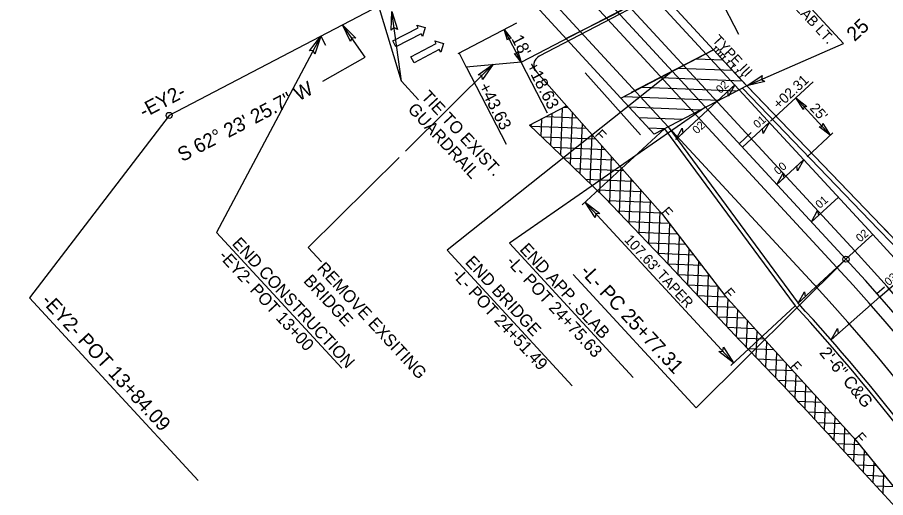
# Model space of a CAD drawing. Extents: x 1702862 to 1704514, y 793768 to 796215.
# Drawn here: x 1703316.6 to 1703743.4, y 794685.6 to 794921.9 of the extents above; entities that cross this region are included whole.
import ezdxf

# ---------------------------------------------------------------- set-up
doc = ezdxf.new("R2010")
doc.units = 0
for name, color, linetype in [('Exist Horizontal Alignment', 7, 'Continuous'), ('Exist Horizontal Alignment Direction Label', 7, 'Continuous'), ('Exist Horizontal Alignment Station Label', 7, 'Continuous'), ('Exist Horizontal Alignment Tick Small', 7, 'Continuous'), ('Old_Level_30', 7, 'Continuous'), ('Prop Approach Slab', 7, 'Continuous'), ('Prop Conc 2ft 6in Curb and Gutter', 7, 'Continuous'), ('Prop Conc Shoulder Berm Gutter', 7, 'Continuous'), ('Prop Dimension', 7, 'Continuous'), ('Prop Dimension Text', 7, 'Continuous'), ('Prop DSN Text', 7, 'Continuous'), ('Prop EOT', 7, 'Continuous'), ('Prop Guardrail', 7, 'Continuous'), ('Prop Guardrail Anchor Unit CELL', 7, 'Continuous'), ('Prop Horizontal Alignment', 7, 'Continuous'), ('Prop Horizontal Alignment Station Label', 7, 'Continuous'), ('Prop Horizontal Alignment Tick Label', 7, 'Continuous'), ('Prop Horizontal Alignment Tick Large', 7, 'Continuous'), ('Prop Horizontal Alignment Tick Small', 7, 'Continuous'), ('Prop Lane Arrow CELL', 7, 'Continuous'), ('Prop Lane Lines', 7, 'Continuous'), ('Prop Leader Line Medium', 7, 'Continuous'), ('Prop Paved Shoulder', 7, 'Continuous'), ('Prop Rem of Exist Asph Pvmt', 7, 'Continuous'), ('Prop Roadway Bridge', 7, 'Continuous'), ('Prop SS Fill Line', 7, 'Continuous'), ('Prop SS Misc', 7, 'Continuous'), ('Prop Structure Anchor Unit CELL', 7, 'Continuous'), ('Prop Superelevation  Arrow CELL', 7, 'Continuous'), ('Prop Superelevation Label', 7, 'Continuous'), ('Prop Terminator CELL', 7, 'Continuous')]:
    doc.layers.add(name, color=color, linetype=linetype)

msp = doc.modelspace()

# ---------------------------------------------------------------- linework, layer by layer
at = {"layer": 'Exist Horizontal Alignment'}
msp.add_line((1703731.56, 795051.6), (1703391.21, 794873.6), dxfattribs=at)
at = {"layer": 'Exist Horizontal Alignment Direction Label'}
msp.add_lwpolyline([(1703466.74, 794890.55), (1703487.62, 794902.29), (1703476.47, 794918.19)], dxfattribs=at)
at = {"layer": 'Exist Horizontal Alignment Station Label'}
msp.add_lwpolyline([(1703391.21, 794873.6), (1703322.49, 794783.98), (1703405.46, 794694.11)], dxfattribs=at)
msp.add_circle((1703391.21, 794873.6), 1.5, dxfattribs=at)
at = {"layer": 'Exist Horizontal Alignment Tick Small'}
msp.add_line((1703465.72, 794912.57), (1703468.04, 794908.14), dxfattribs=at)
at = {"layer": 'Old_Level_30'}
msp.add_line((1703622.97, 794864.03), (1703595.71, 794894.58), dxfattribs=at)
at = {"layer": 'Prop Approach Slab'}
for p, q in [((1703658.78, 794905.92), (1703618.37, 794884.83)), ((1703658.78, 794905.92), (1703675.15, 794888.19)), ((1703650.4, 794901.54), (1703663.3, 794901.02)), ((1703641.5, 794896.89), (1703668.1, 794895.83)), ((1703675.15, 794888.19), (1703629.69, 794864.45)), ((1703632.59, 794892.25), (1703672.89, 794890.63)), ((1703623.69, 794887.6), (1703670.44, 794885.73)), ((1703613.32, 794882.19), (1703629.69, 794864.45)), ((1703614.79, 794882.95), (1703661.54, 794881.08)), ((1703617.33, 794877.84), (1703652.64, 794876.43)), ((1703622.13, 794872.65), (1703643.73, 794871.78)), ((1703626.93, 794867.45), (1703634.83, 794867.14))]:
    msp.add_line(p, q, dxfattribs=at)
msp.add_lwpolyline([(1703658.78, 794905.92), (1703675.15, 794888.19), (1703629.69, 794864.45), (1703613.32, 794882.19)], close=True, dxfattribs=at)
at = {"layer": 'Prop Conc 2ft 6in Curb and Gutter'}
msp.add_line((1703634.75, 794867.09), (1703699, 794779.93), dxfattribs=at)
msp.add_arc((1702985.28, 794122.36), 970.46, 32.25438, 42.65517, dxfattribs=at)
at = {"layer": 'Prop Conc Shoulder Berm Gutter'}
msp.add_line((1703675.15, 794888.19), (1703741.57, 794819.22), dxfattribs=at)
msp.add_arc((1703001.93, 794109.28), 1025.22, 38.16066, 43.82598, dxfattribs=at)
at = {"layer": 'Prop Dimension'}
for p, q in [((1703594.25, 794829.71), (1703634.75, 794867.09)), ((1703595.68, 794831.04), (1703668.69, 794751.95)), ((1703667.25, 794750.62), (1703699, 794779.93))]:
    msp.add_line(p, q, dxfattribs=at)
at = {"layer": 'Prop Dimension Text'}
for p, q in [((1703653.98, 794946.7), (1703671.12, 794913.52)), ((1703533.31, 794904.01), (1703562.18, 794919.2)), ((1703555.92, 794915.89), (1703564.25, 794899.77)), ((1703557.01, 794859.29), (1703537.31, 794897.44)), ((1703577.2, 794874.69), (1703564.25, 794899.77))]:
    msp.add_line(p, q, dxfattribs=at)
at = {"layer": 'Prop EOT'}
for p, q in [((1703259.9, 795332.15), (1703737.14, 794815.13)), ((1703418.98, 795103.79), (1703636.58, 794868.05)), ((1703564.25, 794899.77), (1703653.98, 794946.7)), ((1703533.7, 794904.22), (1703537.26, 794897.42)), ((1703564.25, 794899.77), (1703537.26, 794897.42)), ((1703636.58, 794868.05), (1703700.4, 794781.22))]:
    msp.add_line(p, q, dxfattribs=at)
msp.add_lwpolyline([(1703586.27, 794911.5), (1703608.79, 794922.72), (1703631.89, 794935.05)], dxfattribs=at)
for radius, start, end in [(1018, 14.75888, 42.70907), (968, 32.4282, 42.70916)]:
    msp.add_arc((1702989.11, 794124.65), radius, start, end, dxfattribs=at)
at = {"layer": 'Prop Guardrail'}
msp.add_line((1703741.57, 794819.22), (1703671.5, 794892.15), dxfattribs=at)
msp.add_arc((1703002.29, 794108.92), 1025.21, 38.32941, 43.85449, dxfattribs=at)
at = {"layer": 'Prop Horizontal Alignment'}
msp.add_line((1703246.67, 795319.94), (1703723.92, 794802.92), dxfattribs=at)
msp.add_arc((1702989.11, 794124.65), 1000, 351.25916, 42.70907, dxfattribs=at)
at = {"layer": 'Prop Horizontal Alignment Station Label'}
for p in [(1703723.92, 794802.92), (1703589.75, 794795.36)]:
    msp.add_line(p, (1703650.3, 794729.77), dxfattribs=at)
msp.add_circle((1703723.92, 794802.92), 1.5, dxfattribs=at)
at = {"layer": 'Prop Horizontal Alignment Tick Large'}
msp.add_line((1703671.48, 794859.73), (1703677.36, 794865.16), dxfattribs=at)
at = {"layer": 'Prop Horizontal Alignment Tick Small'}
msp.add_line((1703739.12, 794786.08), (1703742.87, 794789.38), dxfattribs=at)
at = {"layer": 'Prop Lane Arrow CELL'}
for p, q in [((1703513.59, 794916.75), (1703512.9, 794918.08)), ((1703512.9, 794918.08), (1703517.12, 794916.8)), ((1703501.19, 794910.26), (1703513.59, 794916.75)), ((1703515.12, 794913.83), (1703502.72, 794907.34)), ((1703515.82, 794912.5), (1703515.12, 794913.83)), ((1703517.12, 794916.8), (1703515.82, 794912.5)), ((1703502.72, 794907.34), (1703501.19, 794910.26)), ((1703522.46, 794908.94), (1703521.77, 794910.27)), ((1703521.77, 794910.27), (1703526, 794908.99)), ((1703510.06, 794902.45), (1703522.46, 794908.94)), ((1703524, 794906.02), (1703511.59, 794899.52)), ((1703524.69, 794904.69), (1703524, 794906.02)), ((1703526, 794908.99), (1703524.69, 794904.69)), ((1703511.59, 794899.52), (1703510.06, 794902.45))]:
    msp.add_line(p, q, dxfattribs=at)
at = {"layer": 'Prop Lane Lines'}
for p, q in [((1703599.26, 794946.81), (1703728.33, 794806.99)), ((1703591.49, 794937.54), (1703719.51, 794798.85)), ((1703636.58, 794868.05), (1703710.03, 794788.48))]:
    msp.add_line(p, q, dxfattribs=at)
for radius, start in [(1006, 0.00687), (994, 359.40932), (980, 359.40932)]:
    msp.add_arc((1702989.11, 794124.65), radius, start, 42.70907, dxfattribs=at)
at = {"layer": 'Prop Leader Line Medium'}
for p, q in [((1703505.35, 794890.4), (1703492.38, 794933.6)), ((1703505.35, 794890.4), (1703500.62, 794924.67)), ((1703465.72, 794912.57), (1703414.54, 794816.04)), ((1703507.34, 794856.01), (1703550.53, 794898.76)), ((1703638.58, 794895.38), (1703527.8, 794807.39)), ((1703505.35, 794890.4), (1703513.76, 794881.29)), ((1703654.95, 794877.64), (1703558.46, 794810.73)), ((1703459.59, 794808.73), (1703504.23, 794852.93)), ((1703414.54, 794816.04), (1703476.14, 794749.31)), ((1703466.09, 794801.68), (1703459.59, 794808.73)), ((1703527.8, 794807.39), (1703589.4, 794740.66)), ((1703558.46, 794810.73), (1703619.32, 794744.8))]:
    msp.add_line(p, q, dxfattribs=at)
msp.add_lwpolyline([(1703675.15, 794888.19), (1703722.72, 794909.06), (1703678.78, 794956.66)], dxfattribs=at)
at = {"layer": 'Prop Paved Shoulder'}
msp.add_line((1703673, 794887.06), (1703739.89, 794817.6), dxfattribs=at)
msp.add_arc((1703001.93, 794109.28), 1022.89, 38.16066, 43.82598, dxfattribs=at)
at = {"layer": 'Prop Rem of Exist Asph Pvmt'}
for p, q in [((1703584.45, 794877.22), (1703583.53, 794854.21)), ((1703585.42, 794877.73), (1703587.05, 794877.66)), ((1703574.23, 794871.86), (1703573.9, 794863.49)), ((1703576.55, 794873.08), (1703591.64, 794872.47)), ((1703579.34, 794874.54), (1703578.71, 794858.85)), ((1703589.37, 794875.04), (1703588.35, 794849.57)), ((1703568.82, 794868.38), (1703596.23, 794867.29)), ((1703569.12, 794869.19), (1703569.08, 794868.13)), ((1703594.16, 794869.63), (1703593.17, 794844.93)), ((1703574.24, 794863.16), (1703600.82, 794862.1)), ((1703598.94, 794864.22), (1703597.99, 794840.29)), ((1703603.73, 794858.81), (1703602.81, 794835.65)), ((1703579.66, 794857.94), (1703605.41, 794856.91)), ((1703585.08, 794852.72), (1703610, 794851.72)), ((1703608.52, 794853.39), (1703607.62, 794830.82)), ((1703590.5, 794847.5), (1703614.58, 794846.54)), ((1703613.31, 794847.98), (1703612.42, 794825.77)), ((1703595.93, 794842.28), (1703619.17, 794841.35)), ((1703618.09, 794842.57), (1703617.22, 794820.71)), ((1703601.35, 794837.06), (1703623.76, 794836.16)), ((1703622.88, 794837.16), (1703622.02, 794815.66)), ((1703606.65, 794831.84), (1703628.35, 794830.97)), ((1703627.67, 794831.74), (1703626.82, 794810.61)), ((1703611.59, 794826.64), (1703632.94, 794825.79)), ((1703632.46, 794826.33), (1703631.63, 794805.55)), ((1703616.53, 794821.44), (1703637.01, 794820.62)), ((1703637.22, 794820.35), (1703636.43, 794800.5)), ((1703621.47, 794816.24), (1703640.98, 794815.46)), ((1703641.98, 794814.15), (1703641.23, 794795.39)), ((1703626.42, 794811.03), (1703644.94, 794810.29)), ((1703646.73, 794807.96), (1703646.03, 794790.27)), ((1703631.36, 794805.83), (1703648.91, 794805.13)), ((1703636.3, 794800.63), (1703652.87, 794799.97)), ((1703651.49, 794801.77), (1703650.83, 794785.15)), ((1703641.18, 794795.43), (1703656.84, 794794.81)), ((1703656.25, 794795.57), (1703655.62, 794780.04)), ((1703646.06, 794790.23), (1703660.8, 794789.64)), ((1703661, 794789.38), (1703660.42, 794774.92)), ((1703650.94, 794785.03), (1703664.85, 794784.48)), ((1703665.77, 794783.46), (1703665.22, 794769.81)), ((1703655.82, 794779.83), (1703669.55, 794779.29)), ((1703670.56, 794778.17), (1703670.02, 794764.7)), ((1703660.69, 794774.64), (1703674.26, 794774.09)), ((1703675.35, 794772.88), (1703674.83, 794759.67)), ((1703665.57, 794769.44), (1703678.96, 794768.9)), ((1703670.47, 794764.24), (1703683.67, 794763.71)), ((1703680.15, 794767.59), (1703679.63, 794754.65)), ((1703684.94, 794762.31), (1703684.43, 794749.62)), ((1703675.44, 794759.03), (1703688.37, 794758.52)), ((1703689.73, 794757.02), (1703689.23, 794744.59)), ((1703680.41, 794753.83), (1703693.08, 794753.32)), ((1703694.52, 794751.73), (1703694.04, 794739.57)), ((1703685.38, 794748.63), (1703697.79, 794748.13)), ((1703690.35, 794743.42), (1703702.51, 794742.94)), ((1703699.32, 794746.45), (1703698.84, 794734.54)), ((1703704.11, 794741.18), (1703703.64, 794729.5)), ((1703695.32, 794738.22), (1703707.23, 794737.75)), ((1703708.9, 794735.91), (1703708.44, 794724.38)), ((1703700.29, 794733.02), (1703711.96, 794732.55)), ((1703713.7, 794730.64), (1703713.24, 794719.19)), ((1703705.23, 794727.82), (1703716.68, 794727.36)), ((1703710.07, 794722.62), (1703721.41, 794722.17)), ((1703718.49, 794725.37), (1703718.03, 794713.96)), ((1703714.86, 794717.42), (1703726.13, 794716.97)), ((1703723.28, 794720.1), (1703722.83, 794708.7)), ((1703728.08, 794714.84), (1703727.62, 794703.44)), ((1703719.61, 794712.23), (1703730.61, 794711.79)), ((1703732.85, 794709.01), (1703732.41, 794698.21)), ((1703724.34, 794707.04), (1703734.77, 794706.62)), ((1703729.08, 794701.84), (1703738.93, 794701.45)), ((1703737.61, 794703.09), (1703737.21, 794693.01)), ((1703733.85, 794696.65), (1703743.09, 794696.28)), ((1703742.38, 794697.16), (1703742.01, 794687.84)), ((1703738.66, 794691.45), (1703747.25, 794691.11))]:
    msp.add_line(p, q, dxfattribs=at)
for points in [[(1703568.38, 794868.8), (1703586.5, 794878.29)], [(1703579.1, 794858.48), (1703568.38, 794868.8)], [(1703579.1, 794858.48), (1703589.48, 794848.49)], [(1703669.4, 794765.36), (1703636.82, 794800.09), (1703605.39, 794833.16), (1703589.48, 794848.49)]]:
    msp.add_lwpolyline(points, dxfattribs=at)
msp.add_spline([(1703779.68, 794644.96), (1703761.75, 794665.91), (1703731.32, 794699.4), (1703700.82, 794732.47), (1703669.4, 794765.36)], degree=3, dxfattribs=at)
at = {"layer": 'Prop Roadway Bridge'}
for p, q in [((1703525.81, 795049.97), (1703658.78, 794905.92)), ((1703480.41, 795026.18), (1703613.32, 794882.19)), ((1703613.32, 794882.19), (1703658.78, 794905.92))]:
    msp.add_line(p, q, dxfattribs=at)
at = {"layer": 'Prop SS Fill Line'}
for p, q in [((1703689.78, 794963.74), (1703573.15, 794902.74)), ((1703571.72, 794894.99), (1703633.73, 794824.89)), ((1703633.73, 794824.89), (1703664.31, 794785.07)), ((1703664.31, 794785.07), (1703697.03, 794748.96)), ((1703697.03, 794748.96), (1703728.84, 794713.99)), ((1703728.84, 794713.99), (1703758.51, 794677.1))]:
    msp.add_line(p, q, dxfattribs=at)
msp.add_arc((1703575.47, 794898.31), 5, 117.6095, 221.4926, dxfattribs=at)
at = {"layer": 'Prop Structure Anchor Unit CELL'}
for p, q in [((1703658.78, 794905.92), (1703660.25, 794907.28)), ((1703658.78, 794905.92), (1703671.5, 794892.15)), ((1703659.84, 794904.78), (1703661.31, 794906.13)), ((1703659.86, 794907.7), (1703660.64, 794906.86)), ((1703660.92, 794906.55), (1703661.7, 794905.71)), ((1703661.98, 794905.41), (1703662.76, 794904.56)), ((1703660.9, 794903.63), (1703662.37, 794904.98)), ((1703661.96, 794902.48), (1703663.43, 794903.84)), ((1703663.02, 794901.33), (1703664.49, 794902.69)), ((1703663.04, 794904.26), (1703663.82, 794903.42)), ((1703664.1, 794903.11), (1703664.88, 794902.27)), ((1703666.22, 794900.81), (1703667, 794899.97)), ((1703665.14, 794899.04), (1703666.61, 794900.39)), ((1703667.26, 794896.74), (1703668.73, 794898.1)), ((1703668.34, 794898.52), (1703669.12, 794897.68)), ((1703669.38, 794894.44), (1703670.85, 794895.8)), ((1703670.46, 794896.22), (1703671.23, 794895.38)), ((1703671.5, 794892.15), (1703672.97, 794893.5)), ((1703672.58, 794893.92), (1703673.35, 794893.08))]:
    msp.add_line(p, q, dxfattribs=at)
at = {"layer": 'Prop Superelevation  Arrow CELL'}
for p, q in [((1703656.09, 794876.4), (1703669.31, 794888.61)), ((1703640.32, 794861.85), (1703656.09, 794876.4)), ((1703673.05, 794858.03), (1703686.27, 794870.24)), ((1703690, 794839.66), (1703703.23, 794851.87)), ((1703706.96, 794821.29), (1703720.19, 794833.5)), ((1703723.92, 794802.92), (1703737.14, 794815.13)), ((1703723.92, 794802.92), (1703700.48, 794781.29)), ((1703740.64, 794784.34), (1703754.17, 794796.22)), ((1703740.64, 794784.34), (1703716.65, 794763.28))]:
    msp.add_line(p, q, dxfattribs=at)
for points in [[(1703669.31, 794888.61), (1703666.26, 794883.07), (1703665.92, 794885.48)], [(1703640.32, 794861.85), (1703643.37, 794867.39), (1703643.72, 794864.98)], [(1703686.27, 794870.24), (1703683.22, 794864.7), (1703682.87, 794867.11)], [(1703703.23, 794851.87), (1703700.18, 794846.33), (1703699.83, 794848.74)], [(1703690, 794839.66), (1703693.05, 794845.2), (1703693.4, 794842.8)], [(1703706.96, 794821.29), (1703710.01, 794826.83), (1703710.36, 794824.43)], [(1703700.48, 794781.29), (1703703.53, 794786.83), (1703703.87, 794784.42)], [(1703716.65, 794763.28), (1703719.84, 794768.75), (1703720.13, 794766.34)]]:
    msp.add_lwpolyline(points, close=True, dxfattribs=at)
at = {"layer": 'Prop Superelevation Label'}
for p, q in [((1703686.79, 794870.72), (1703707.87, 794890.18)), ((1703699.24, 794882.21), (1703716.21, 794863.85)), ((1703704.77, 794853.3), (1703717.55, 794865.09))]:
    msp.add_line(p, q, dxfattribs=at)
for points in [[(1703702.97, 794876.47), (1703699.24, 794882.21), (1703704.73, 794878.04), (1703703.26, 794877.86)], [(1703712.48, 794869.6), (1703716.21, 794863.85), (1703710.72, 794868.02), (1703712.19, 794868.2)]]:
    msp.add_lwpolyline(points, close=True, dxfattribs=at)
at = {"layer": 'Prop Terminator CELL'}
for points in [[(1703500.32, 794915.54), (1703500.62, 794924.67), (1703503.45, 794915.92), (1703501.7, 794916.85)], [(1703480.37, 794909.93), (1703476.47, 794918.19), (1703482.97, 794911.7), (1703481, 794911.72)], [(1703557.57, 794910.66), (1703555.92, 794915.89), (1703559.27, 794911.51), (1703558.1, 794911.68)], [(1703460.12, 794905.35), (1703465.72, 794912.57), (1703462.88, 794903.83), (1703462.01, 794905.6)], [(1703562.59, 794905), (1703564.25, 794899.77), (1703560.9, 794904.16), (1703562.07, 794903.98)], [(1703543.04, 794893.53), (1703550.53, 794898.76), (1703545.22, 794891.26), (1703544.92, 794893.21)], [(1703684.02, 794890.38), (1703675.15, 794888.19), (1703682.8, 794893.29), (1703682.39, 794891.36)], [(1703600.65, 794823.37), (1703595.68, 794831.04), (1703603, 794825.47), (1703601.04, 794825.23)], [(1703663.72, 794759.61), (1703668.69, 794751.95), (1703661.38, 794757.51), (1703663.33, 794757.75)]]:
    msp.add_lwpolyline(points, close=True, dxfattribs=at)

# ---------------------------------------------------------------- texts
at = {"layer": 'Exist Horizontal Alignment Direction Label'}
for s, p in [('S 62%%d 23\' 25.7" W', (1703397.64, 794850.61)), ('-EY2-', (1703378.79, 794872.12))]:
    msp.add_text(s, height=7, rotation=27.6095, dxfattribs=at).set_placement(p)
at = {"layer": 'Exist Horizontal Alignment Station Label'}
msp.add_text('-EY2- POT 13+84.09', height=7, rotation=312.7091, dxfattribs=at).set_placement((1703327.94, 794782.11))
at = {"layer": 'Prop Dimension Text'}
for s, height, rotation, p in [("18'", 6, 297.3125, (1703559.27, 794911.42)), ('+18.63', 6, 297.3125, (1703566.56, 794898.04)), ('+43.63', 6, 297.3125, (1703543.14, 794887.88)), ('TIE TO EXIST.', 6, 312.7091, (1703514.72, 794882.5)), ('GUARDRAIL', 6, 312.7091, (1703508.11, 794876.4)), ("107.63' TAPER", 5, 312.7091, (1703614.62, 794812.2)), ('REMOVE EXSITING', 6, 312.7091, (1703463.48, 794798.1)), ('BRIDGE', 6, 312.7091, (1703456.87, 794791.99)), ('2\'-6" C&G', 6, 309.2167, (1703710.55, 794756.76))]:
    msp.add_text(s, height=height, rotation=rotation, dxfattribs=at).set_placement(p)
at = {"layer": 'Prop DSN Text'}
for s, height, p in [('@ APPR SLAB LT.', 5, (1703676.2, 794950.45)), ('END CONSTRUCTION', 6, (1703421.77, 794810.32)), ('END APP. SLAB', 6, (1703563.19, 794807.46)), ('-EY2- POT 13+00', 6, (1703415.15, 794804.22)), ('END BRIDGE', 6, (1703536.36, 794801.21)), ('-L- POT 24+75.63', 6, (1703556.58, 794801.36)), ('-L- POT 24+51.49', 6, (1703529.75, 794795.11))]:
    msp.add_text(s, height=height, rotation=312.7091, dxfattribs=at).set_placement(p)
at = {"layer": 'Prop Guardrail Anchor Unit CELL'}
msp.add_text('TYPE III', height=5, rotation=312.7301, dxfattribs=at).set_placement((1703657.91, 794910.4))
at = {"layer": 'Prop Horizontal Alignment Station Label'}
msp.add_text('-L- PC 25+77.31', height=7, rotation=312.7091, dxfattribs=at).set_placement((1703592.8, 794796.58))
at = {"layer": 'Prop Horizontal Alignment Tick Label'}
msp.add_text('25', height=7, rotation=42.7091, dxfattribs=at).set_placement((1703728.18, 794909.69))
at = {"layer": 'Prop SS Misc'}
for rotation, p in [(312.7091, (1703600.18, 794863.89)), (311.4091, (1703632.79, 794825.95)), (311.4091, (1703663.37, 794786.13)), (311.4091, (1703696.09, 794750.03)), (311.4091, (1703727.91, 794715.06))]:
    msp.add_text('F', height=5, rotation=rotation, dxfattribs=at).set_placement(p)
at = {"layer": 'Prop Superelevation Label'}
for s, height, rotation, p in [('+02.31', 5, 42.7097, (1703690.92, 794876.4)), ('02', 4, 42.7091, (1703662.23, 794884.17)), ("25'", 5, 312.1969, (1703705.81, 794876.95)), ('01', 4, 40.7995, (1703680.48, 794867.02)), ('02', 4, 42.7091, (1703650.64, 794864.23)), ('00', 4, 40.7995, (1703690.64, 794844.2)), ('01', 4, 40.7995, (1703711.01, 794827.59)), ('02', 4, 40.7995, (1703730.91, 794811.09)), ('03', 4, 41.2768, (1703744.98, 794789.6))]:
    msp.add_text(s, height=height, rotation=rotation, dxfattribs=at).set_placement(p)

doc.saveas('drawing.dxf')
